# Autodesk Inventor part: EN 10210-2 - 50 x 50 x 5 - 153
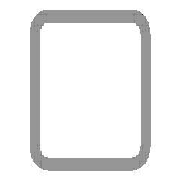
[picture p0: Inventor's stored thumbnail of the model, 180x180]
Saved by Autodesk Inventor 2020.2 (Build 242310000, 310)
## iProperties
IsCustomPart: 1
_CCFamilyMember: 16
_CCFamilyDisplayName: DIN EN 10210-2 (USAS B17.1 quadratisch) - Rohrleitung — In Klammern angegebene Größen wurden aufgehoben
_FrameMemberDoc: Frame Member File
_Version: 15.0.0
_GetPNFromCC: 1
Created: 2019-10
Part Number: EN 10210-2 - 50 x 50 x 5 - 153
Material: Stahl, weich
Description: Rohrleitung
Document SubType Name: Modeling
Standard: DIN
Designer: lutzd
Standard Revision: 2006-07
Standards Organization: DIN
Language: de-DE
Size Designation: 50 x 50 x 5
Categories: <MemberInstance><Categories><Category DisplayName="Profile" InternalName="089c4875-fa83-4c05-b084-43b9cc11f5ed" Mnemonic="GRDR"><CategoryParameter DisplayName="
Stock Number: 50 x 50 x 5
Mass: 1048.73 g
Surface Area: 535.429 cm^2
Volume: 133.596 cm^3
Density: 7.85 g/cm^3
Appearance: Semi-Polished(8)
G_L: 153,000 mm
G_W: 50,000 mm
G_H: 50,000 mm
Dimensions: 50x50x153 mm
Mass: 1,049 kg
DocNumber: ADSK-014283
Folder: .
+F201DCE3-DECD-48FD-8130-F56700F2F324+SCHNITTDETAIL1: Schnittwinkel 90,00 grd
+1093EA2D-6B37-4C62-9268-1D0093E9F647+SCHNITTDETAIL2: Schnittwinkel 90,00 grd
VLT_Material: Stahl, weich
Title: Profil-Bauteil
Author: lutzd
Revision Number: -
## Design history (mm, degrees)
node "Startebene"
node "Endebene"
sketch "Skizze"
  geometry: L1 (-25, -17.5)-(-25, 17.5); L2 (-17.5, 25)-(17.5, 25); L3 (25, 17.5)-(25, -17.5); L4 (17.5, -25)-(-17.5, -25); L5 (-15, 20)-(15, 20); L6 (20, 15)-(20, -15); L7 (15, -20)-(-15, -20); L8 (-20, -15)-(-20, 15); L9 (0, 37.175)-(0, -37.175) reference; L10 (-37.175, 0)-(37.175, 0) reference; A1 r 7.5 centre (-17.5, -17.5) between (-25, -17.5) and (-17.5, -25); A2 r 7.5 centre (-17.5, 17.5) between (-17.5, 25) and (-25, 17.5); A3 r 7.5 centre (17.5, 17.5) between (25, 17.5) and (17.5, 25); A4 r 7.5 centre (17.5, -17.5) between (17.5, -25) and (25, -17.5); A5 r 5 centre (-15, -15) between (-20, -15) and (-15, -20); A6 r 5 centre (-15, 15) between (-15, 20) and (-20, 15); A7 r 5 centre (15, 15) between (20, 15) and (15, 20); A8 r 5 centre (15, -15) between (15, -20) and (20, -15)
  constraints: 16 end point, 16 point on circle, 16 tangent, 8 centre point, 6 equal radius, 4 parallel, 2 perpendicular, 2 other
  dimensions: "d7" = 7.5 radius of A1 (= G_IR); "d10" = 50 distance between parallel lines of L2 L4 (= G_H); "d11" = 50 distance between parallel lines of L1 L3 (= G_W); "d12" = 5 distance between parallel lines of L3 L6 (= G_T); "d15" = 25 distance between parallel lines of L2 L10 (= 0.5 x d10); "d16" = 25 distance between parallel lines of L9 L3 (= 0.5 x d11); "d19" = 5 radius of A5 (= G_T); "d20" = 5 distance between parallel lines of L4 L7 (= G_T)
extrude "Körper" new body sketch "Skizze" stored distance "d3" = 153 (= G_L); taper "d4" = 0 deg
node "Driven Length"
  sketch "Sketch3"
    geometry: L1 (0, 0)-(10, 0) reference
    constraints: 2 end point, 1 horizontal
  workplane "Work Plane3"
  sketch "Sketch4"
    geometry: L1 (-2, 50)-(12, 50) reference; L2 (-2, 203)-(12, 203) reference
    dimensions: "d18" = 153 distance between parallel lines of L1 L2 (derived)
workplane "Arbeitsebene4"
feature "Trennen1"
workplane "Arbeitsebene5"
feature "Trennen2"
body "Solid1"
other parameters: "G_W" = 50 [user parameter; used in 1 equation term], "G_H" = 50 [user parameter; used in 1 equation term], "G_T" = 5 [user parameter; used in 3 equation terms], "G_IR" = 7.5 [user parameter; used in 1 equation term], "G_L" = 153 (= d18) [user parameter; used in 1 equation term], "d14" = 203 (= G_OFFSET_END + B_L), "B_L" = 253 [user parameter; used in 1 equation term], "d17" = 90 deg
